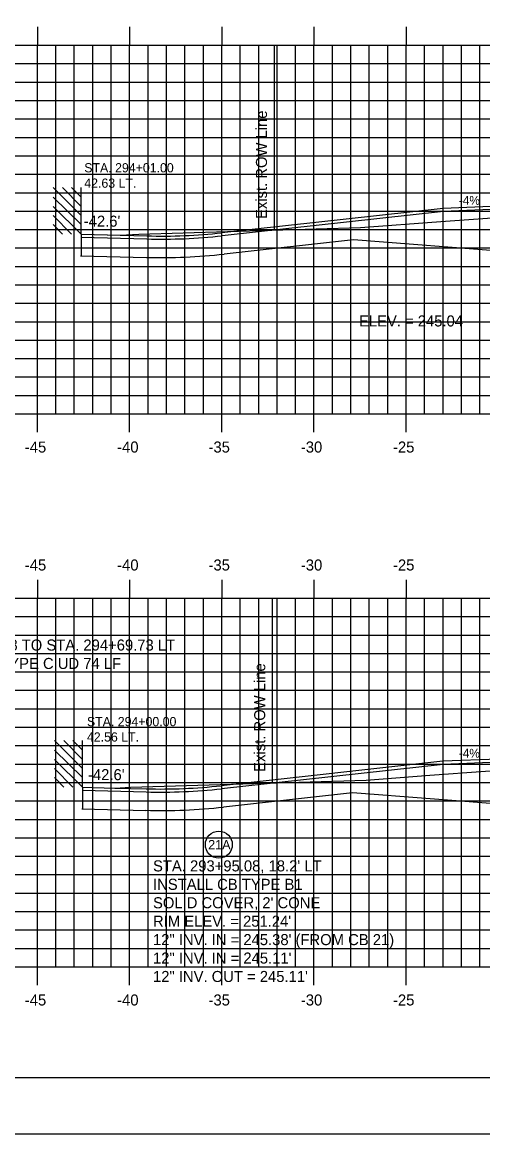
# Model space of a CAD drawing. Extents: x 859129 to 859299, y 366268 to 366378.
# Drawn here: x 859166.6 to 859191.6, y 366268.2 to 366328.5 of the extents above; entities that cross this region are included whole.
import ezdxf

# ---------------------------------------------------------------- set-up
doc = ezdxf.new("R2010")
doc.units = 0
for name, color, linetype in [('ANNOTATION', 7, 'Continuous'), ('BORDER', 7, 'Continuous'), ('D_Drainage_Text', 7, 'Continuous'), ('D_Roadway_Drive_Gravel_LT', 7, 'Continuous'), ('D_Roadway_Drive_SubGrade', 7, 'Continuous'), ('D_Text_Monospaced', 7, 'Continuous'), ('D_Text_Standard', 7, 'Continuous'), ('E_ROW_Line', 7, 'Continuous'), ('H_V ANNOTATION', 7, 'Continuous'), ('MAJOR', 7, 'Continuous'), ('MINOR', 7, 'Continuous'), ('PLOT BOUNDARY', 7, 'Continuous'), ('S_Buildings', 7, 'Continuous'), ('S_Roadway_Centerline', 7, 'Continuous')]:
    doc.layers.add(name, color=color, linetype=linetype)

msp = doc.modelspace()

# ---------------------------------------------------------------- linework, layer by layer
at = {"layer": 'ANNOTATION'}
for p, q in [((859189.477, 366318.215), (859177.476, 366316.895)), ((859189.475, 366288.22), (859177.439, 366286.896))]:
    msp.add_line(p, q, dxfattribs=at)
at = {"layer": 'BORDER'}
msp.add_line((859137.462, 366271.236), (859297.462, 366271.236), dxfattribs=at)
at = {"layer": 'D_Drainage_Text'}
msp.add_circle((859177.301, 366283.866), 0.731, dxfattribs=at)
at = {"layer": 'D_Roadway_Drive_Gravel_LT'}
for p, q in [((859192.463, 366318.501), (859189.459, 366318.381)), ((859189.459, 366318.381), (859177.458, 366317.06)), ((859192.47, 366318.334), (859189.459, 366318.214)), ((859169.827, 366316.816), (859173.398, 366316.724)), ((859184.612, 366316.674), (859177.585, 366315.901)), ((859169.801, 366315.817), (859173.372, 366315.724)), ((859189.457, 366288.386), (859177.42, 366287.062)), ((859192.462, 366288.506), (859189.457, 366288.386)), ((859192.468, 366288.339), (859189.457, 366288.219)), ((859169.902, 366286.815), (859173.361, 366286.725)), ((859184.557, 366286.673), (859177.548, 366285.902)), ((859169.876, 366285.815), (859173.335, 366285.725))]:
    msp.add_line(p, q, dxfattribs=at)
for points in [[(859169.832, 366316.983), (859173.402, 366316.891)], [(859169.906, 366286.981), (859171.66, 366286.936), (859173.365, 366286.892)]]:
    msp.add_lwpolyline(points, dxfattribs=at)
for centre, radius, start in [((859174.177, 366346.881), 30.167, 268.51981), ((859174.177, 366346.881), 30, 268.51981), ((859174.177, 366346.881), 31.167, 268.51981), ((859174.14, 366316.882), 30.167, 268.51964), ((859174.14, 366316.882), 30, 268.51964), ((859174.14, 366316.882), 31.167, 268.51964)]:
    msp.add_arc(centre, radius, start, 276.2773, dxfattribs=at)
at = {"layer": 'D_Roadway_Drive_SubGrade'}
for p, q in [((859169.832, 366316.983), (859169.832, 366315.816)), ((859193.284, 366316.004), (859184.612, 366316.674)), ((859169.906, 366286.981), (859169.906, 366285.814)), ((859193.184, 366286.007), (859184.557, 366286.673))]:
    msp.add_line(p, q, dxfattribs=at)
at = {"layer": 'E_ROW_Line'}
for p, q in [((859180.313, 366317.21), (859180.313, 366327.21)), ((859180.217, 366287.217), (859180.217, 366297.217))]:
    msp.add_line(p, q, dxfattribs=at)
at = {"layer": 'MAJOR'}
for p, q in [((859167.462, 366328.238), (859167.462, 366327.236)), ((859172.462, 366328.238), (859172.462, 366327.236)), ((859177.462, 366328.238), (859177.462, 366327.236)), ((859182.462, 366328.238), (859182.462, 366327.236)), ((859187.462, 366328.238), (859187.462, 366327.236)), ((859142.462, 366327.236), (859282.462, 366327.236)), ((859142.462, 366327.236), (859282.462, 366327.236)), ((859167.462, 366307.236), (859167.462, 366327.236)), ((859172.462, 366307.236), (859172.462, 366327.236)), ((859177.462, 366307.236), (859177.462, 366327.236)), ((859182.462, 366307.236), (859182.462, 366327.236)), ((859187.462, 366307.236), (859187.462, 366327.236)), ((859142.462, 366322.236), (859282.462, 366322.236)), ((859142.462, 366317.236), (859282.462, 366317.236)), ((859142.462, 366312.236), (859282.462, 366312.236)), ((859142.462, 366307.236), (859282.462, 366307.236)), ((859142.462, 366307.236), (859282.462, 366307.236)), ((859167.462, 366306.234), (859167.462, 366307.236)), ((859172.462, 366306.234), (859172.462, 366307.236)), ((859177.462, 366306.234), (859177.462, 366307.236)), ((859182.462, 366306.234), (859182.462, 366307.236)), ((859187.462, 366306.234), (859187.462, 366307.236)), ((859167.462, 366298.238), (859167.462, 366297.236)), ((859172.462, 366298.238), (859172.462, 366297.236)), ((859177.462, 366298.238), (859177.462, 366297.236)), ((859182.462, 366298.238), (859182.462, 366297.236)), ((859187.462, 366298.238), (859187.462, 366297.236)), ((859142.462, 366297.236), (859282.462, 366297.236)), ((859142.462, 366297.236), (859282.462, 366297.236)), ((859167.462, 366277.236), (859167.462, 366297.236)), ((859172.462, 366277.236), (859172.462, 366297.236)), ((859177.462, 366277.236), (859177.462, 366297.236)), ((859182.462, 366277.236), (859182.462, 366297.236)), ((859187.462, 366277.236), (859187.462, 366297.236)), ((859142.462, 366292.236), (859282.462, 366292.236)), ((859142.462, 366287.236), (859282.462, 366287.236)), ((859142.462, 366282.236), (859282.462, 366282.236)), ((859142.462, 366277.236), (859282.462, 366277.236)), ((859142.462, 366277.236), (859282.462, 366277.236)), ((859167.462, 366276.234), (859167.462, 366277.236)), ((859172.462, 366276.234), (859172.462, 366277.236)), ((859177.462, 366276.234), (859177.462, 366277.236)), ((859182.462, 366276.234), (859182.462, 366277.236)), ((859187.462, 366276.234), (859187.462, 366277.236))]:
    msp.add_line(p, q, dxfattribs=at)
at = {"layer": 'MINOR'}
for p, q in [((859168.462, 366307.236), (859168.462, 366327.236)), ((859169.462, 366307.236), (859169.462, 366327.236)), ((859170.462, 366307.236), (859170.462, 366327.236)), ((859171.462, 366307.236), (859171.462, 366327.236)), ((859173.462, 366307.236), (859173.462, 366327.236)), ((859174.462, 366307.236), (859174.462, 366327.236)), ((859175.462, 366307.236), (859175.462, 366327.236)), ((859176.462, 366307.236), (859176.462, 366327.236)), ((859178.462, 366307.236), (859178.462, 366327.236)), ((859179.462, 366307.236), (859179.462, 366327.236)), ((859180.462, 366307.236), (859180.462, 366327.236)), ((859181.462, 366307.236), (859181.462, 366327.236)), ((859183.462, 366307.236), (859183.462, 366327.236)), ((859184.462, 366307.236), (859184.462, 366327.236)), ((859185.462, 366307.236), (859185.462, 366327.236)), ((859186.462, 366307.236), (859186.462, 366327.236)), ((859188.462, 366307.236), (859188.462, 366327.236)), ((859189.462, 366307.236), (859189.462, 366327.236)), ((859190.462, 366307.236), (859190.462, 366327.236)), ((859191.462, 366307.236), (859191.462, 366327.236)), ((859142.462, 366326.236), (859282.462, 366326.236)), ((859142.462, 366325.236), (859282.462, 366325.236)), ((859142.462, 366324.236), (859282.462, 366324.236)), ((859142.462, 366323.236), (859282.462, 366323.236)), ((859142.462, 366321.236), (859282.462, 366321.236)), ((859142.462, 366320.236), (859282.462, 366320.236)), ((859142.462, 366319.236), (859282.462, 366319.236)), ((859142.462, 366318.236), (859282.462, 366318.236)), ((859142.462, 366316.236), (859282.462, 366316.236)), ((859142.462, 366315.236), (859282.462, 366315.236)), ((859142.462, 366314.236), (859282.462, 366314.236)), ((859142.462, 366313.236), (859282.462, 366313.236)), ((859142.462, 366311.236), (859282.462, 366311.236)), ((859142.462, 366310.236), (859282.462, 366310.236)), ((859142.462, 366309.236), (859282.462, 366309.236)), ((859142.462, 366308.236), (859282.462, 366308.236)), ((859168.462, 366277.236), (859168.462, 366297.236)), ((859169.462, 366277.236), (859169.462, 366297.236)), ((859170.462, 366277.236), (859170.462, 366297.236)), ((859171.462, 366277.236), (859171.462, 366297.236)), ((859173.462, 366277.236), (859173.462, 366297.236)), ((859174.462, 366277.236), (859174.462, 366297.236)), ((859175.462, 366277.236), (859175.462, 366297.236)), ((859176.462, 366277.236), (859176.462, 366297.236)), ((859178.462, 366277.236), (859178.462, 366297.236)), ((859179.462, 366277.236), (859179.462, 366297.236)), ((859180.462, 366277.236), (859180.462, 366297.236)), ((859181.462, 366277.236), (859181.462, 366297.236)), ((859183.462, 366277.236), (859183.462, 366297.236)), ((859184.462, 366277.236), (859184.462, 366297.236)), ((859185.462, 366277.236), (859185.462, 366297.236)), ((859186.462, 366277.236), (859186.462, 366297.236)), ((859188.462, 366277.236), (859188.462, 366297.236)), ((859189.462, 366277.236), (859189.462, 366297.236)), ((859190.462, 366277.236), (859190.462, 366297.236)), ((859191.462, 366277.236), (859191.462, 366297.236)), ((859142.462, 366296.236), (859282.462, 366296.236)), ((859142.462, 366295.236), (859282.462, 366295.236)), ((859142.462, 366294.236), (859282.462, 366294.236)), ((859142.462, 366293.236), (859282.462, 366293.236)), ((859142.462, 366291.236), (859282.462, 366291.236)), ((859142.462, 366290.236), (859282.462, 366290.236)), ((859142.462, 366289.236), (859282.462, 366289.236)), ((859142.462, 366288.236), (859282.462, 366288.236)), ((859142.462, 366286.236), (859282.462, 366286.236)), ((859142.462, 366285.236), (859282.462, 366285.236)), ((859142.462, 366284.236), (859282.462, 366284.236)), ((859142.462, 366283.236), (859282.462, 366283.236)), ((859142.462, 366281.236), (859282.462, 366281.236)), ((859142.462, 366280.236), (859282.462, 366280.236)), ((859142.462, 366279.236), (859282.462, 366279.236)), ((859142.462, 366278.236), (859282.462, 366278.236))]:
    msp.add_line(p, q, dxfattribs=at)
at = {"layer": 'PLOT BOUNDARY'}
msp.add_lwpolyline([(859129.368, 366268.177), (859299.368, 366268.177), (859299.368, 366378.177), (859129.368, 366378.177)], close=True, dxfattribs=at)
at = {"layer": 'S_Buildings'}
for p, q in [((859169.832, 366318), (859168.322, 366319.509)), ((859169.832, 366318.492), (859168.814, 366319.509)), ((859169.832, 366318.984), (859169.307, 366319.509)), ((859169.832, 366316.983), (859169.832, 366319.509)), ((859169.832, 366317.508), (859168.322, 366318.984)), ((859169.832, 366316.983), (859168.322, 366318.492)), ((859169.307, 366316.983), (859168.322, 366318)), ((859168.814, 366316.983), (859168.322, 366317.508)), ((859169.906, 366287.998), (859168.397, 366289.507)), ((859169.906, 366288.49), (859168.889, 366289.507)), ((859169.906, 366288.982), (859169.381, 366289.507)), ((859169.906, 366286.981), (859169.906, 366289.507)), ((859169.906, 366287.506), (859168.397, 366288.982)), ((859169.906, 366286.981), (859168.397, 366288.49)), ((859169.381, 366286.981), (859168.397, 366287.998)), ((859168.889, 366286.981), (859168.397, 366287.506))]:
    msp.add_line(p, q, dxfattribs=at)
at = {"layer": 'S_Roadway_Centerline'}
for points in [[(859169.832, 366316.983), (859171.943, 366316.928), (859172.963, 366316.992), (859184.977, 366317.349), (859189.338, 366317.678), (859196.931, 366318.222), (859197.329, 366318.256), (859197.347, 366318.256), (859197.482, 366318.259), (859201.989, 366318.366), (859206.908, 366318.407), (859213.218, 366318.491), (859217.013, 366318.39), (859222.407, 366318.303), (859223.494, 366318.328), (859225.019, 366318.299), (859225.438, 366318.377), (859225.757, 366318.383), (859227.301, 366318.615), (859228.452, 366318.772), (859236.7, 366318.584), (859249.126, 366317.989), (859257.602, 366317.315), (859264.492, 366316.922)], [(859169.906, 366286.981), (859171.66, 366286.936), (859172.507, 366286.988), (859185.297, 366287.368), (859188.748, 366287.629), (859194.777, 366288.061), (859197.182, 366288.265), (859197.292, 366288.264), (859198.102, 366288.284), (859201.989, 366288.376), (859206.239, 366288.411), (859213.208, 366288.504), (859217.392, 366288.393), (859222.394, 366288.312), (859223.589, 366288.339), (859225, 366288.313), (859225.461, 366288.398), (859225.72, 366288.403), (859227.504, 366288.671), (859228.402, 366288.793), (859238.08, 366288.573), (859248.539, 366288.071), (859258.988, 366287.239), (859264.658, 366286.917)]]:
    msp.add_lwpolyline(points, dxfattribs=at)

# ---------------------------------------------------------------- texts
at = {"layer": 'D_Drainage_Text'}
for s, p in [('STA. 293+97.08 TO STA. 294+69.73 LT', (859160.567, 366294.393)), ('INSTALL 12" TYPE C UD 74 LF', (859160.567, 366293.393)), ("STA. 293+95.08, 18.2' LT", (859173.731, 366282.411)), ('INSTALL CB TYPE B1', (859173.731, 366281.411)), ("SOLID COVER, 2' CONE", (859173.731, 366280.411)), ("RIM ELEV. = 251.24'", (859173.731, 366279.411)), ('12" INV. IN = 245.38\' (FROM CB 21)', (859173.731, 366278.411)), ('12" INV. IN = 245.11\'', (859173.731, 366277.411)), ('12" INV. OUT = 245.11\'', (859173.731, 366276.411))]:
    msp.add_text(s, height=0.6, dxfattribs=at).set_placement(p)
at = {"layer": 'D_Roadway_Drive_Gravel_LT'}
for p in [(859190.318, 366318.577), (859190.316, 366288.582)]:
    msp.add_text('-4%', height=0.48, dxfattribs=at).set_placement(p)
at = {"layer": 'D_Text_Monospaced'}
for s, height, p in [('STA. 294+01.00', 0.49998, (859170.003, 366320.337)), ('42.63 LT.', 0.5, (859170.003, 366319.503)), ('STA. 294+00.00', 0.49998, (859170.148, 366290.29)), ('42.56 LT.', 0.5, (859170.148, 366289.456))]:
    msp.add_text(s, height=height, dxfattribs=at).set_placement(p)
at = {"layer": 'D_Text_Standard'}
for s, p in [("-42.6'", (859169.976, 366317.39)), ('ELEV. = 245.04', (859184.901, 366311.976)), ("-42.6'", (859170.207, 366287.362))]:
    msp.add_text(s, height=0.6, dxfattribs=at).set_placement(p)
at = {"layer": 'E_ROW_Line'}
for p in [(859179.913, 366317.81), (859179.817, 366287.817)]:
    msp.add_text('Exist. ROW Line', height=0.6, rotation=90, dxfattribs=at).set_placement(p)
at = {"layer": 'H_V ANNOTATION'}
for s, height, p in [('-45', 0.6, (859166.779, 366305.136)), ('-40', 0.6, (859171.787, 366305.136)), ('-35', 0.6, (859176.742, 366305.136)), ('-30', 0.6, (859181.75, 366305.136)), ('-25', 0.6, (859186.747, 366305.136)), ('-45', 0.6, (859166.779, 366298.736)), ('-40', 0.6, (859171.787, 366298.736)), ('-35', 0.6, (859176.742, 366298.736)), ('-30', 0.6, (859181.75, 366298.736)), ('-25', 0.6, (859186.747, 366298.736)), ('21A', 0.51, (859176.723, 366283.607)), ('-45', 0.6, (859166.779, 366275.136)), ('-40', 0.6, (859171.787, 366275.136)), ('-35', 0.6, (859176.742, 366275.136)), ('-30', 0.6, (859181.75, 366275.136)), ('-25', 0.6, (859186.747, 366275.136))]:
    msp.add_text(s, height=height, dxfattribs=at).set_placement(p)

doc.saveas('drawing.dxf')
